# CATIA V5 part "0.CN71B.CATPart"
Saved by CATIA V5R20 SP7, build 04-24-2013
Part number: 0.CN71B
Material "Nessuno"
Bounding box of the stored display mesh (mm): x 0 to 149.213, y -135.185 to 0, z -56.919 to 41.584
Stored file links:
  C:\Users\designer2\Desktop\Ottobre 2022\25-10-2022\04\Yori Evo 48V\0.CN71B.CATPart
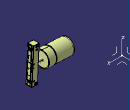
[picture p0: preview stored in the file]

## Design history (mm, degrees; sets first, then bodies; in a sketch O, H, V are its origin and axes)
AxisSystem1: origin (0, 0, 0), X (1, 0, 0), Y (0, 1, 0), Z (0, 0, 1)
Set1
  DatumSurface1
Body1 (main body), material "Nessuno"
